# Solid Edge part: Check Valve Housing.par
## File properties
Title: Check Valve Housing
Author: Dan
Template: Normal.par
Last saved by: Dan
Revision: 19
Application: Solid Edge
Density: 0 kg/mm^3
Accuracy: 0.99
Document Number: P52-017
Project Name: Piston Pump P52
Material: steel
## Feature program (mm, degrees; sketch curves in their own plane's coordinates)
sketch for "unnamed Protrusion 1" plane through (0, 0, 0) normal (1, 0, 0) x-axis (0, 1, 0)
  circle centre (0, 0) radius 10
extrude "unnamed Protrusion 1" add finite 37.8 along -normal
sketch for "unnamed RevolvedCutout 1" plane through (0, 0, 0) normal (0, -1, 0) x-axis (1, 0, 0)
  line (0, 7.25) -> (-20.3, 7.25)
  line (-20.3, 7.25) -> (-20.3, 7.9393)
  line (-20.3, 7.9393) -> (-21.3607, 9)
  line (-21.3607, 9) -> (-26.1738, 9)
  line (-26.1738, 9) -> (-27.0738, 8.1)
  line (-27.0738, 8.1) -> (-28.5, 8.1)
  line (-28.5, 8.1) -> (-29.366, 9.6)
  line (-29.366, 9.6) -> (-37.8, 9.6)
  dimension (linear) = 20.3
  dimension (linear) = 28.5
revolve "unnamed RevolvedCutout 1" cut full turn 360 deg
sketch for "ExtrudedCutout_1" plane through (-37.8, 0, 0) normal (-1, 0, 0) x-axis (0, -1, 0)
  line (-3.7528, -6.5) -> (3.7528, -6.5)
  line (3.7528, -6.5) -> (7.5056, 0)
  line (7.5056, 0) -> (3.7528, 6.5)
  line (3.7528, 6.5) -> (-3.7528, 6.5)
  line (-3.7528, 6.5) -> (-7.5056, 0)
  line (-7.5056, 0) -> (-3.7528, -6.5)
extrude "ExtrudedCutout_1" cut finite 7.3 along -normal
sketch for "ExtrudedCutout_2" plane through (-37.8, 0, 0) normal (-1, 0, 0) x-axis (0, -1, 0)
  circle centre (0, 0) radius 5
extrude "ExtrudedCutout_2" cut finite 3 along -normal
sketch for "Hole_1" plane through (0, 0, 0) normal (1, 0, 0) x-axis (0, 1, 0)
  hole centre (0, 0) bore radius 3.5
hole "Hole_1" diameter 7 through  CounterBoreDepth = 20.5 mm; CounterSinkAngle = 118 deg
sketch for "Hole_2" plane through (0, 0, 0) normal (0, 0, 1) x-axis (1, 0, 0)
  hole centre (-17.5, 0) bore radius 2.5
hole "Hole_2" diameter 5 through
sketch for "Hole_3" plane through (0, 0, 0) normal (0, 0, 1) x-axis (1, 0, 0)
  hole centre (-3.1, 0) bore radius 1.55
hole "Hole_3" diameter 3.1 through
chamfer "Chamfer_1" setback 0.6
thread "unnamed Thread 1"
fillet "Round_1" radius 0.5
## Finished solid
Body 1: solid body, 31 faces, 46 edges, 12 vertices.
  Faces by surface: cylinder 11, plane 11, cone 8, torus 1
  Edges by curve: circle 20, line 18, intersection 8
Bounding box of the edges (mm; curved faces can reach further): 37.800 x 19.200 x 19.200, from (-37.8, -9.6, -9.6) to (0, 9.6, 9.6).
Cylindrical faces by radius (mm): R1.55 x2, R2.5 x2, R3.5 x1, R5 x1, R5.1 x1, R7.25 x1, R8.1 x1, R9 x1, R9.6 x1
Conical faces (half-angle, radius in mm at the cone's reference point): 45 deg R3.5 x1, 45 deg R5 x1, 45 deg R5.7 x1, 45 deg R7.25 x1, 45 deg R7.9393 x1, 45 deg R9 x1, 59 deg R5.1 x1, 60 deg R8.1 x1
Toroidal faces (ring radius, tube radius in mm): R4 r0.5 x1
Planar faces by outward normal: +x 2, +z 1, -x 3, -z 1, oblique 4
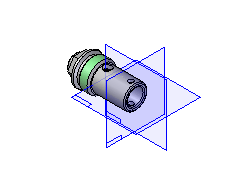
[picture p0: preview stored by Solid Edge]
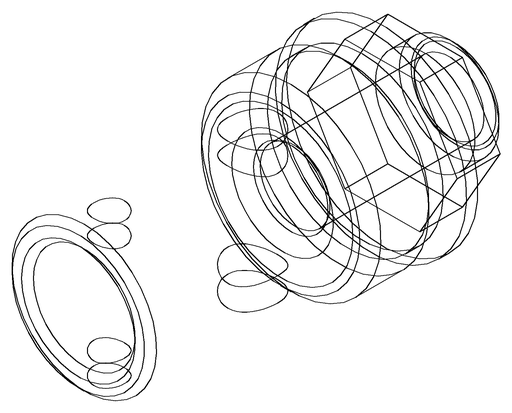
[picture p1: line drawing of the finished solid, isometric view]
